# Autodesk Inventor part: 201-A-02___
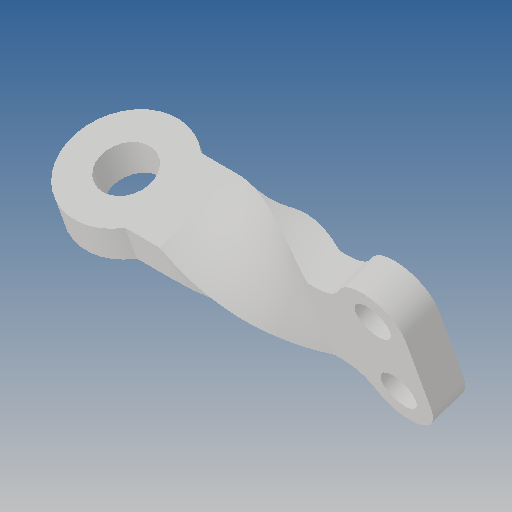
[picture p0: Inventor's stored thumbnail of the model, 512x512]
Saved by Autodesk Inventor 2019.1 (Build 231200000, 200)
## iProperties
Created: 2010-06
Part Number: 201-A-02___
Material: Ogólny
Document SubType Name: Modeling
Designer: CADENGINEERING4
Density: 1 g/cm^3
Appearance: Domyślna
Author: CADENGINEERING4
Revision Number: ANY
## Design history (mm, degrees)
feature "NONE"
node "Bryła1"
